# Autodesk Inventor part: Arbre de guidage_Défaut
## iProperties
Shininess: 64.0
Length Units: 11269
Angle Units: 11279
Time Units: 11290
Mass Units: 11283
Length Display Precision: 3
Angle Display Precision: 2
Compacted: True
Part Number: Arbre de guidage_Défaut
Document SubType Name: Modeling
Created: 2006-11
Material: Par défaut
Designer: profs_sti
Density: 0.0
Volumn: 0.0
Area: 0.0
PropertySet Name: Model Information
Control State: 0
Master: False
Checked Out: False
Author: profs_sti
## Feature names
1. Base1
